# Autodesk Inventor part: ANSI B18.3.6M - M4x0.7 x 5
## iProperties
Comments: To add or edit properties for Autodesk Inventor files, use iProperties.
Created: 2004-07
Part Number: ANSI B18.3.6M - M4x0.7 x 5
Vendor: Autodesk Inc.
Document SubType Name: Modeling
Designer: John Blackburn
Material: Default
Description: Type I - Forged Hexagon Socket Set Screw - Cup Point - Metric
Standard: ANSI B18.3.6M
Size Designation: M4x0.7 x 5
Alert: To add or edit properties for Autodesk Inventor files, use iProperties.
Control State: 0
Master: False
Checked Out: False
Shininess: 64.0
Length Units: 11269
Angle Units: 11279
Time Units: 11290
Mass Units: 11283
Length Display Precision: 3
Angle Display Precision: 2
Compacted: True
EGR: 1
Density: 0.0
Volumn: 0.0
Area: 0.0
PropertySet Name: Model Information
Author: John Blackburn
Revision Number: 8
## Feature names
1. Body [Revolution]
2. Slot [Extrusion]
3. Chamfer1
4. Chamfer2
